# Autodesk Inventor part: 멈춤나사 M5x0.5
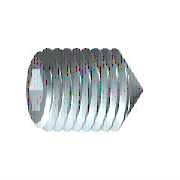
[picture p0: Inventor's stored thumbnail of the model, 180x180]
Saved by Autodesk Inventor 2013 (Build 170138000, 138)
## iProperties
Company: 한국ATC센터
IsCustomPart: 1
Created: 2014-11
Part Number: 멈춤나사 M5x0.5
Material: Steel, Mild
Description: 6각 소켓 머리 없는 멈춤 나사
Document SubType Name: Modeling
Standard: KS B 1028
Designer: KYOUNG IL JANG
Standards Organization: KS
Language: ko-KR
Size Designation: 원추점 M5x10
Categories: <MemberInstance><Categories><Category DisplayName="조임쇠" InternalName="e4da775c-781d-43d5-af7c-5136215cf5a6" Mnemonic="FSTN"><Category DisplayName="볼트" InternalN
Density: 7.86 g/cm^3
Mass: 1.16912 g
Surface Area: 1.91683 cm^2
Volume: 0.148743 cm^3
Author: KYOUNG IL JANG
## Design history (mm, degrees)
revolve "본체" stored, may be unused: angle "d6" = 90 deg
sketch "스케치2"
  geometry: L1 (-0.722, 1.25)-(0.722, 1.25); L2 (0.722, 1.25)-(1.443, 0); L3 (1.443, 0)-(0.722, -1.25); L4 (0.722, -1.25)-(-0.722, -1.25); L5 (-0.722, -1.25)-(-1.443, 0); L6 (-1.443, 0)-(-0.722, 1.25); 3 further points
  constraints: 12 end point, 1 coincident, 1 horizontal, 13 other
extrude "슬롯" join sketch "스케치2" taper "d7" = 0 deg; stored distance "d21" = 10
workaxis "Work Axis1"
workplane "Work Plane1"
body "Solid1"
feature "스레드" dims "d12" = 10 (= NLG), "d13" = 0
chamfer "모따기1" distance "d8" = 2.25 (computed from NND, SPD, FAWI); stored, may be unused: angle "d9" = 45 deg (= FAWI), second distance "d34" = 2.25 (computed from NND, SPD, FAWI)
chamfer "모따기2" distance "d10" = 0.49076 (= -0.5 x GD1 + 0.5 x NND); stored, may be unused: angle "d11" = 45 deg (= FAWI), second distance "d35" = 0.49076 (= -0.5 x GD1 + 0.5 x NND)
sketch "스케치1"
  geometry: L1 (0, 0)-(6.167, 0); L2 (10, 1.443)-(10, 2.5); L3 (10, 2.5)-(0, 2.5); L4 (10, 1.443)-(7, 1.443); L5 (7, 1.443)-(6.167, 0); L6 (0, -0.5)-(0, 3) reference; L7 (0, 2.5)-(0, 0)
  constraints: 13 end point, 3 parallel, 1 collinear, 1 perpendicular, 1 point on line
  dimensions: "d0" = 3 distance of L2.start L4.end (= INTI); "d1" = 60 deg angle of L5 L1; "d2" = 5 diameter of L3 L1 (= NND); "d3" = 2.88675 diameter of L4 L1 (= 1.1547 x SW); "d5" = 10 distance from line of L2 L3.end (= NLG)
other parameters: "NND" = 5 [user parameter; used in 5 equation terms], "NLG" = 10 [user parameter; used in 2 equation terms], "INTI" = 3 [user parameter; used in 1 equation term], "FAWI" = 45 deg [user parameter; used in 4 equation terms], "SW" = 2.5 [user parameter; used in 2 equation terms], "GD1" = 4.01848 (= THREADDIA - 1.2269 x PTC) [user parameter; used in 2 equation terms], "d4" = 0, "FAWI1" = 45 deg [user parameter], "SPD" = 0.5 [user parameter; used in 2 equation terms], "d36" = 0, "d37" = 0, "GUL" = 0.49076 (= 0.61345 x PTC) [user parameter], "TPU" = 12.5 (computed from PTC) [user parameter], "TOA" = 30 deg [user parameter], "THREADDIA" = 5 [user parameter; used in 1 equation term], "PTC" = 0.8 [user parameter; used in 4 equation terms], "GAL" = 0.49076 (= 0.61345 x PTC) [user parameter], "E0" = 2.8875 (= 1.155 x SW) [user parameter]
